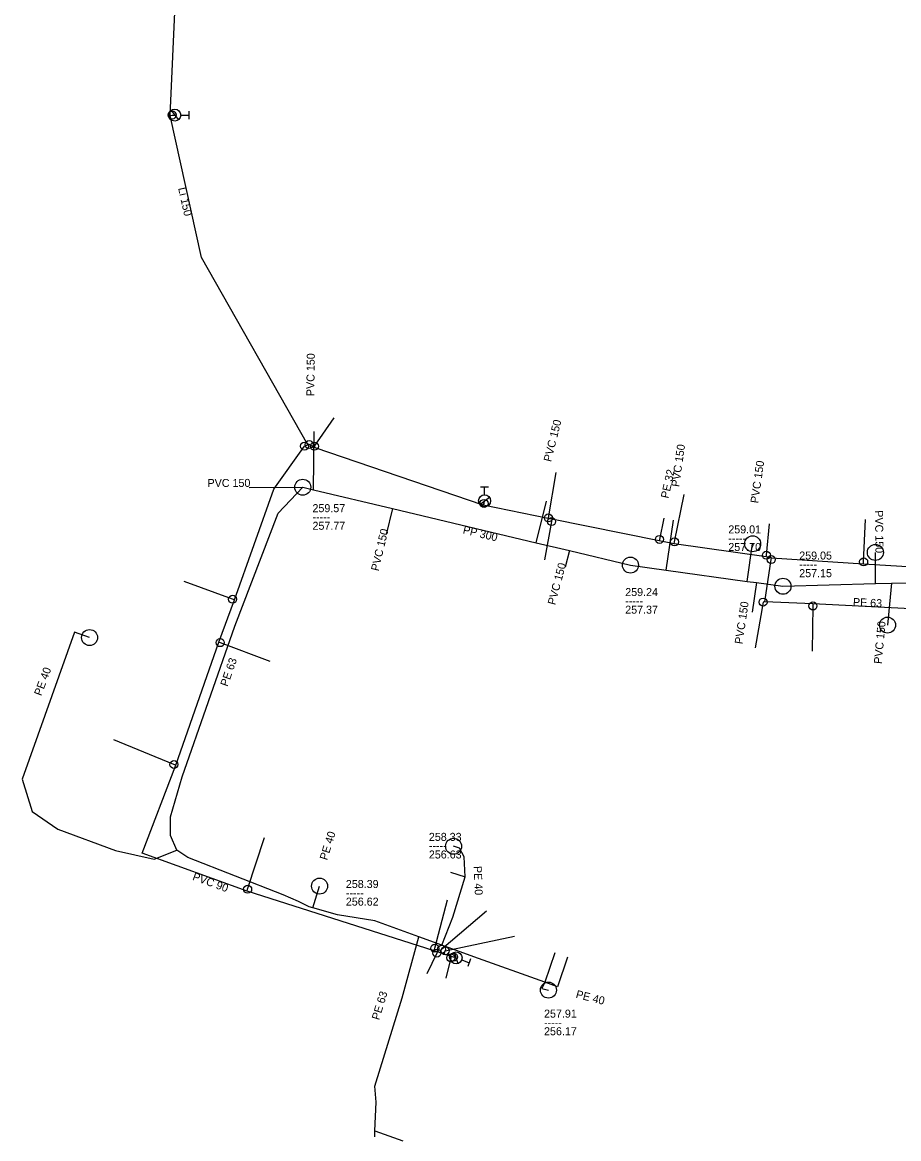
# Model space of a CAD drawing. Extents: x -770828 to -770111, y -1050344 to -1049447.
# Drawn here: x -770633.3 to -770523.9, y -1050195 to -1050055.5 of the extents above; entities that cross this region are included whole.
import ezdxf

# ---------------------------------------------------------------- set-up
doc = ezdxf.new("R2010")
doc.units = 0
doc.layers.add('Level 0', color=7, linetype='Continuous')

msp = doc.modelspace()

# ---------------------------------------------------------------- linework, layer by layer
at = {"layer": 'Level 0'}
for p, q in [((-770614.88, -1050067.15), (-770614.13, -1050050.69)), ((-770614.77, -1050066.53), (-770613.85, -1050067.71)), ((-770612.56, -1050066.62), (-770612.56, -1050067.62)), ((-770614.88, -1050067.15), (-770614.63, -1050067.11)), ((-770610.95, -1050084.91), (-770614.88, -1050067.15)), ((-770614.63, -1050067.11), (-770614.31, -1050067.12)), ((-770613.56, -1050067.12), (-770612.56, -1050067.12)), ((-770597.69, -1050108.29), (-770610.95, -1050084.91)), ((-770596.86, -1050108.49), (-770594.37, -1050104.95)), ((-770596.96, -1050113.93), (-770596.88, -1050106.66)), ((-770601.94, -1050113.83), (-770598.09, -1050108.47)), ((-770598.09, -1050108.47), (-770597.69, -1050108.29)), ((-770597.52, -1050108.28), (-770597.69, -1050108.29)), ((-770596.78, -1050108.67), (-770597.52, -1050108.28)), ((-770596.78, -1050108.67), (-770596.86, -1050108.49)), ((-770575.78, -1050115.86), (-770596.78, -1050108.67)), ((-770567.63, -1050117.44), (-770566.66, -1050111.76)), ((-770606.85, -1050127.67), (-770601.94, -1050113.83)), ((-770605.01, -1050113.63), (-770598.32, -1050113.61)), ((-770601.39, -1050116.85), (-770598.32, -1050113.61)), ((-770598.32, -1050113.61), (-770596.96, -1050113.93)), ((-770596.96, -1050113.93), (-770587.12, -1050116.27)), ((-770576.09, -1050113.55), (-770575.09, -1050113.55)), ((-770575.59, -1050114.55), (-770575.59, -1050113.55)), ((-770576.18, -1050115.76), (-770575, -1050114.84)), ((-770575.78, -1050115.86), (-770575.67, -1050115.63)), ((-770575.67, -1050115.63), (-770575.59, -1050115.3)), ((-770569.17, -1050120.53), (-770567.88, -1050115.33)), ((-770551.87, -1050120.43), (-770550.67, -1050114.53)), ((-770606.82, -1050130.94), (-770601.39, -1050116.85)), ((-770587.12, -1050116.27), (-770587.89, -1050119.52)), ((-770587.12, -1050116.27), (-770569.17, -1050120.53)), ((-770567.64, -1050117.5), (-770575.78, -1050115.86)), ((-770567.23, -1050117.9), (-770568.11, -1050122.69)), ((-770567.64, -1050117.5), (-770567.63, -1050117.44)), ((-770567.18, -1050117.6), (-770567.64, -1050117.5)), ((-770567.18, -1050117.6), (-770567.23, -1050117.9)), ((-770553.79, -1050120.3), (-770567.18, -1050117.6)), ((-770553.21, -1050117.48), (-770553.75, -1050120.12)), ((-770552.9, -1050123.95), (-770552, -1050117.72)), ((-770540.39, -1050122.1), (-770540, -1050118.17)), ((-770528.24, -1050122.93), (-770528.03, -1050117.65)), ((-770569.17, -1050120.53), (-770565, -1050121.52)), ((-770553.75, -1050120.12), (-770553.79, -1050120.3)), ((-770551.92, -1050120.68), (-770553.79, -1050120.3)), ((-770551.92, -1050120.68), (-770551.87, -1050120.43)), ((-770540.41, -1050122.32), (-770551.92, -1050120.68)), ((-770542.78, -1050125.36), (-770542.11, -1050120.67)), ((-770565, -1050121.52), (-770565.55, -1050123.59)), ((-770565, -1050121.52), (-770557.38, -1050123.33)), ((-770540.57, -1050127.93), (-770539.79, -1050122.65)), ((-770540.41, -1050122.32), (-770540.39, -1050122.1)), ((-770539.76, -1050122.41), (-770540.41, -1050122.32)), ((-770539.79, -1050122.65), (-770539.76, -1050122.41)), ((-770539.76, -1050122.41), (-770528.25, -1050123.18)), ((-770526.74, -1050125.65), (-770526.78, -1050121.75)), ((-770557.38, -1050123.33), (-770552.9, -1050123.95)), ((-770552.9, -1050123.95), (-770542.78, -1050125.36)), ((-770528.25, -1050123.18), (-770528.24, -1050122.93)), ((-770528.25, -1050123.18), (-770516.49, -1050123.86)), ((-770607.08, -1050127.59), (-770613.14, -1050125.4)), ((-770542.78, -1050125.36), (-770541.63, -1050125.52)), ((-770524.78, -1050125.6), (-770518.03, -1050125.41)), ((-770541.63, -1050125.52), (-770542.18, -1050129.23)), ((-770541.63, -1050125.52), (-770538.32, -1050125.98)), ((-770538.32, -1050125.98), (-770526.74, -1050125.65)), ((-770526.74, -1050125.65), (-770524.78, -1050125.6)), ((-770524.78, -1050125.6), (-770525.26, -1050130.82)), ((-770608.82, -1050132.95), (-770606.85, -1050127.67)), ((-770606.85, -1050127.67), (-770607.08, -1050127.59)), ((-770540.81, -1050127.96), (-770541.78, -1050133.67)), ((-770540.57, -1050127.93), (-770540.81, -1050127.96)), ((-770534.58, -1050128.19), (-770540.57, -1050127.93)), ((-770534.58, -1050128.19), (-770534.58, -1050128.44)), ((-770519.68, -1050128.92), (-770534.58, -1050128.19)), ((-770534.58, -1050128.44), (-770534.69, -1050134.1)), ((-770613.37, -1050149.78), (-770606.82, -1050130.94)), ((-770626.83, -1050131.71), (-770633.35, -1050150.09)), ((-770624.95, -1050132.38), (-770626.83, -1050131.71)), ((-770614.18, -1050148.34), (-770608.82, -1050132.95)), ((-770608.82, -1050132.95), (-770608.63, -1050133.02)), ((-770608.63, -1050133.02), (-770602.44, -1050135.33)), ((-770614.41, -1050148.24), (-770621.9, -1050145.17)), ((-770618.38, -1050159.3), (-770614.18, -1050148.34)), ((-770614.18, -1050148.34), (-770614.41, -1050148.24)), ((-770633.35, -1050150.09), (-770632.1, -1050154.12)), ((-770614.83, -1050154.77), (-770613.37, -1050149.78)), ((-770632.1, -1050154.12), (-770628.9, -1050156.32)), ((-770614.83, -1050157.1), (-770614.83, -1050154.77)), ((-770628.9, -1050156.32), (-770621.72, -1050158.99)), ((-770614.04, -1050158.95), (-770614.83, -1050157.1)), ((-770605.2, -1050163.83), (-770603.09, -1050157.36)), ((-770578.74, -1050158.7), (-770579.47, -1050158.46)), ((-770578.13, -1050159.76), (-770578.74, -1050158.7)), ((-770621.72, -1050158.99), (-770616.86, -1050160.06)), ((-770605.28, -1050164.08), (-770618.38, -1050159.3)), ((-770616.86, -1050160.06), (-770614.04, -1050158.95)), ((-770612.66, -1050159.87), (-770614.04, -1050158.95)), ((-770600.75, -1050164.52), (-770612.66, -1050159.87)), ((-770578.03, -1050162.29), (-770578.13, -1050159.76)), ((-770579.87, -1050161.68), (-770578.03, -1050162.29)), ((-770579.55, -1050167.31), (-770578.03, -1050162.29)), ((-770605.28, -1050164.08), (-770605.2, -1050163.83)), ((-770581.9, -1050171.52), (-770605.28, -1050164.08)), ((-770598.85, -1050165.34), (-770600.75, -1050164.52)), ((-770597.07, -1050166.16), (-770596.21, -1050163.43)), ((-770597.51, -1050166.04), (-770598.85, -1050165.34)), ((-770581.82, -1050171.2), (-770580.24, -1050165.13)), ((-770597.07, -1050166.16), (-770597.51, -1050166.04)), ((-770593.96, -1050167), (-770597.07, -1050166.16)), ((-770589.31, -1050167.77), (-770593.96, -1050167)), ((-770580.97, -1050171.32), (-770575.37, -1050166.5)), ((-770580.92, -1050170.81), (-770579.55, -1050167.31)), ((-770583.82, -1050169.76), (-770589.31, -1050167.77)), ((-770585.91, -1050177.37), (-770583.82, -1050169.76)), ((-770580.92, -1050170.81), (-770583.82, -1050169.76)), ((-770580.53, -1050171.5), (-770571.88, -1050169.7)), ((-770581.9, -1050171.52), (-770581.82, -1050171.2)), ((-770581.11, -1050171.77), (-770580.97, -1050171.32)), ((-770576.95, -1050172.25), (-770580.92, -1050170.81)), ((-770581.56, -1050171.8), (-770582.82, -1050174.37)), ((-770581.49, -1050171.65), (-770581.9, -1050171.52)), ((-770581.49, -1050171.65), (-770581.56, -1050171.8)), ((-770581.11, -1050171.77), (-770581.49, -1050171.65)), ((-770580.65, -1050171.92), (-770581.11, -1050171.77)), ((-770580.65, -1050171.92), (-770580.53, -1050171.5)), ((-770579.86, -1050172.17), (-770580.65, -1050171.92)), ((-770579.82, -1050172.39), (-770580.46, -1050174.92)), ((-770579.86, -1050172.17), (-770579.82, -1050172.39)), ((-770579.48, -1050172.29), (-770579.86, -1050172.17)), ((-770579.16, -1050172.4), (-770579.48, -1050172.29)), ((-770579.39, -1050171.69), (-770578.93, -1050173.11)), ((-770578.46, -1050172.66), (-770577.52, -1050173)), ((-770577.34, -1050172.53), (-770577.69, -1050173.47)), ((-770568.06, -1050175.45), (-770576.95, -1050172.25)), ((-770566.83, -1050171.78), (-770568.06, -1050175.45)), ((-770565.25, -1050172.31), (-770566.5, -1050176.03)), ((-770568.06, -1050175.45), (-770568.44, -1050176.21)), ((-770566.5, -1050176.03), (-770568.06, -1050175.45)), ((-770568.44, -1050176.21), (-770567.62, -1050176.42)), ((-770589.3, -1050188.42), (-770585.91, -1050177.37)), ((-770589.16, -1050190.43), (-770589.3, -1050188.42)), ((-770589.3, -1050194.01), (-770589.16, -1050190.43)), ((-770589.32, -1050194.73), (-770589.3, -1050194.01)), ((-770589.3, -1050194.01), (-770585.82, -1050195.23))]:
    msp.add_line(p, q, dxfattribs=at)
for centre, radius in [((-770614.63, -1050067.11), 0.5), ((-770614.31, -1050067.12), 0.75), ((-770598.09, -1050108.47), 0.5), ((-770597.52, -1050108.28), 0.5), ((-770596.86, -1050108.49), 0.5), ((-770598.32, -1050113.61), 1), ((-770575.59, -1050115.3), 0.75), ((-770575.67, -1050115.63), 0.5), ((-770567.63, -1050117.44), 0.5), ((-770567.23, -1050117.9), 0.5), ((-770553.75, -1050120.12), 0.5), ((-770542.11, -1050120.67), 1), ((-770551.87, -1050120.43), 0.5), ((-770526.78, -1050121.75), 1), ((-770557.38, -1050123.33), 1), ((-770540.39, -1050122.1), 0.5), ((-770539.79, -1050122.65), 0.5), ((-770528.24, -1050122.93), 0.5), ((-770538.32, -1050125.98), 1), ((-770607.08, -1050127.59), 0.5), ((-770540.81, -1050127.96), 0.5), ((-770534.58, -1050128.44), 0.5), ((-770525.26, -1050130.82), 1), ((-770624.95, -1050132.38), 1), ((-770608.63, -1050133.02), 0.5), ((-770614.41, -1050148.24), 0.5), ((-770579.47, -1050158.46), 1), ((-770596.21, -1050163.43), 1), ((-770605.2, -1050163.83), 0.5), ((-770581.82, -1050171.2), 0.5), ((-770581.56, -1050171.8), 0.5), ((-770580.97, -1050171.32), 0.5), ((-770580.53, -1050171.5), 0.5), ((-770579.82, -1050172.39), 0.5), ((-770579.48, -1050172.29), 0.5), ((-770579.16, -1050172.4), 0.75), ((-770567.62, -1050176.42), 1)]:
    msp.add_circle(centre, radius, dxfattribs=at)

# ---------------------------------------------------------------- texts
for s, rotation, p in [('Li 150', 282.478, (-770613.89, -1050076.25)), ('PVC 150', 89.37, (-770596.87, -1050102.23)), ('PVC 150', 76.068, (-770567.28, -1050110.5)), ('PVC 150', 81.78, (-770551.3, -1050113.61)), ('PE 32', 77.471, (-770552.63, -1050115.06)), ('PVC 150', 81.87, (-770541.41, -1050115.66)), ('PVC 150', 0.171, (-770610.21, -1050113.58)), ('PVC 150', 270.588, (-770526.82, -1050116.49)), ('PP 300', 346.649, (-770578.38, -1050119.37)), ('PVC 150', 76.671, (-770588.84, -1050124.14)), ('PVC 150', 75.12, (-770566.78, -1050128.38)), ('PVC 150', 81.567, (-770543.38, -1050133.25)), ('PE 63', 357.195, (-770529.6, -1050128.43)), ('PVC 150', 84.746, (-770525.98, -1050135.71)), ('PE 63', 70.804, (-770607.71, -1050138.57)), ('PE 40', 69.614, (-770630.98, -1050139.74)), ('PE 40', 72.515, (-770595.28, -1050160.26)), ('PVC 90', 339.954, (-770612.17, -1050162.63)), ('PE 40', 272.263, (-770576.96, -1050160.94)), ('PE 63', 73.058, (-770588.77, -1050180.23)), ('PE 40', 345.635, (-770564.27, -1050177.37))]:
    msp.add_text(s, height=1, rotation=rotation, dxfattribs=at).set_placement(p)
for s, p in [('259.57', (-770597.1, -1050116.72)), ('-----', (-770597.1, -1050117.82)), ('257.77', (-770597.1, -1050118.92)), ('259.01', (-770545.15, -1050119.37)), ('-----', (-770545.15, -1050120.47)), ('257.70', (-770545.15, -1050121.57)), ('259.05', (-770536.29, -1050122.64)), ('-----', (-770536.29, -1050123.74)), ('257.15', (-770536.29, -1050124.84)), ('259.24', (-770558.03, -1050127.2)), ('-----', (-770558.03, -1050128.3)), ('257.37', (-770558.03, -1050129.4)), ('258.33', (-770582.56, -1050157.78)), ('-----', (-770582.56, -1050158.88)), ('256.63', (-770582.56, -1050159.98)), ('258.39', (-770592.93, -1050163.67)), ('-----', (-770592.93, -1050164.77)), ('256.62', (-770592.93, -1050165.87)), ('257.91', (-770568.17, -1050179.86)), ('-----', (-770568.17, -1050180.96)), ('256.17', (-770568.17, -1050182.06))]:
    msp.add_text(s, height=1, dxfattribs=at).set_placement(p)

doc.saveas('drawing.dxf')
